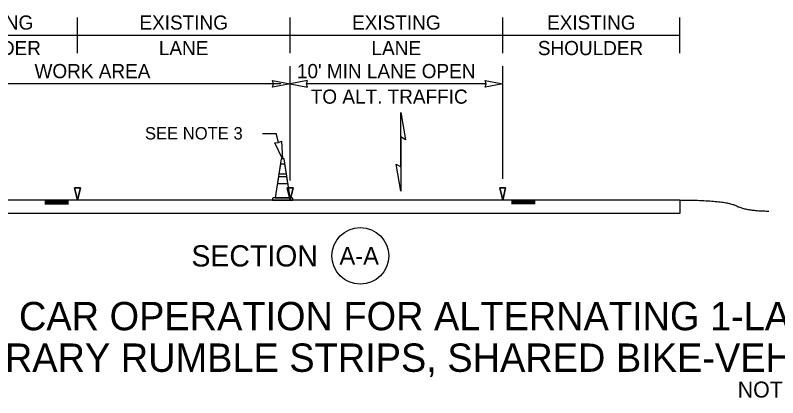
# Model space of a CAD drawing. Extents: x 99999.1 to 100095.7, y 99995 to 100010.7.
# Drawn here: x 100004.94 to 100009.243, y 100001.18 to 100003.339 of the extents above; entities that cross this region are included whole.
import ezdxf

# ---------------------------------------------------------------- set-up
doc = ezdxf.new("R2010")
doc.units = 0
for name, color, linetype in [('SH_DE_DetailHeading1Text', 7, 'Continuous'), ('TR_WZ_TrafficConeElev', 7, 'Continuous'), ('TR_WZ_WorkZoneDetails', 7, 'Continuous'), ('TR_WZ_WorkZoneTextCurrent', 7, 'Continuous')]:
    doc.layers.add(name, color=color, linetype=linetype)

msp = doc.modelspace()

# ---------------------------------------------------------------- linework, layer by layer
at = {"layer": 'TR_WZ_TrafficConeElev'}
for p, q in [((100006.4363, 100002.4976), (100006.428, 100002.4434)), ((100006.4616, 100002.4976), (100006.4363, 100002.4976)), ((100006.4699, 100002.4434), (100006.4616, 100002.4976)), ((100006.4255, 100002.4268), (100006.4197, 100002.3893)), ((100006.4724, 100002.4268), (100006.4255, 100002.4268)), ((100006.428, 100002.4434), (100006.4699, 100002.4434)), ((100006.4782, 100002.3893), (100006.4724, 100002.4268)), ((100006.4197, 100002.3893), (100006.4782, 100002.3893)), ((100006.3953, 100002.308), (100006.3911, 100002.3038)), ((100006.3911, 100002.3038), (100006.3911, 100002.2955)), ((100006.3911, 100002.2955), (100006.5068, 100002.2955)), ((100006.4073, 100002.308), (100006.3953, 100002.308)), ((100006.5068, 100002.3038), (100006.5026, 100002.308)), ((100006.5068, 100002.2955), (100006.5068, 100002.3038))]:
    msp.add_line(p, q, dxfattribs=at)
msp.add_lwpolyline([(100006.4073, 100002.308), (100006.4906, 100002.308), (100006.4568, 100002.5288), (100006.4411, 100002.5288)], close=True, dxfattribs=at)
msp.add_lwpolyline([(100006.4073, 100002.308), (100006.4906, 100002.308), (100006.4568, 100002.5288), (100006.4411, 100002.5288)], close=True, dxfattribs=at)
msp.add_lwpolyline([(100006.5026, 100002.308), (100006.4906, 100002.308), (100006.4073, 100002.308)], dxfattribs=at)
at = {"layer": 'TR_WZ_WorkZoneDetails'}
for p, q in [((100005.2907, 100003.1255), (100005.2907, 100003.3255)), ((100006.4907, 100003.1255), (100006.4907, 100003.3255)), ((100007.6907, 100003.1255), (100007.6907, 100003.3255)), ((100008.6907, 100003.1255), (100008.6907, 100003.3255)), ((100004.2907, 100003.2255), (100005.2907, 100003.2255)), ((100005.2907, 100003.2255), (100006.4907, 100003.2255)), ((100006.4907, 100003.2255), (100007.6907, 100003.2255)), ((100007.6907, 100003.2255), (100008.6907, 100003.2255)), ((100006.4907, 100002.4052), (100006.4907, 100003.0515)), ((100007.6907, 100002.4152), (100007.6907, 100003.0515)), ((100006.4387, 100002.9515), (100004.3844, 100002.9515)), ((100007.597, 100002.9515), (100006.5844, 100002.9515)), ((100006.3358, 100002.6715), (100006.412, 100002.6715)), ((100006.4255, 100002.6196), (100006.412, 100002.6715)), ((100007.1157, 100002.6519), (100007.1157, 100002.4831)), ((100007.1157, 100002.4831), (100007.1157, 100002.6519)), ((100008.6907, 100002.2954), (100004.2907, 100002.2954)), ((100005.1077, 100002.2902), (100005.2407, 100002.2902)), ((100005.1077, 100002.2846), (100005.2407, 100002.2846)), ((100005.1077, 100002.2789), (100005.2407, 100002.2789)), ((100007.8737, 100002.2898), (100007.7407, 100002.2898)), ((100007.8737, 100002.2842), (100007.7407, 100002.2842)), ((100007.8737, 100002.2785), (100007.7407, 100002.2785)), ((100008.6907, 100002.2954), (100008.6907, 100002.2204)), ((100005.1077, 100002.2737), (100005.2407, 100002.2737)), ((100007.8737, 100002.2733), (100007.7407, 100002.2733)), ((100008.6907, 100002.2204), (100004.2907, 100002.2204))]:
    msp.add_line(p, q, dxfattribs=at)
for points in [[(100006.4907, 100002.9515), (100006.3924, 100002.9322), (100006.397, 100002.9515), (100006.3924, 100002.9708)], [(100006.4907, 100002.9515), (100006.589, 100002.9322), (100006.5844, 100002.9515), (100006.589, 100002.9708)], [(100007.6907, 100002.9515), (100007.5924, 100002.9322), (100007.597, 100002.9515), (100007.5924, 100002.9708)], [(100007.1157, 100002.7895), (100007.1427, 100002.6363), (100007.1157, 100002.6519)], [(100006.449, 100002.5288), (100006.4057, 100002.6192), (100006.4255, 100002.6196), (100006.443, 100002.6288)], [(100007.1157, 100002.3454), (100007.0887, 100002.4987), (100007.1157, 100002.4831)], [(100005.2907, 100002.2954), (100005.274, 100002.3652), (100005.3073, 100002.3652)], [(100006.4907, 100002.2954), (100006.474, 100002.3652), (100006.5074, 100002.3652)], [(100007.6907, 100002.2954), (100007.674, 100002.3652), (100007.7073, 100002.3652)]]:
    msp.add_lwpolyline(points, close=True, dxfattribs=at)
for points in [[(100005.3073, 100002.3652), (100005.274, 100002.3652), (100005.2907, 100002.2954), (100005.3073, 100002.3652)], [(100006.5074, 100002.3652), (100006.474, 100002.3652), (100006.4907, 100002.2954), (100006.5074, 100002.3652)], [(100007.7073, 100002.3652), (100007.674, 100002.3652), (100007.6907, 100002.2954), (100007.7073, 100002.3652)]]:
    msp.add_lwpolyline(points, dxfattribs=at)
msp.add_circle((100006.8872, 100001.9805), 0.16, dxfattribs=at)
msp.add_open_spline([(100008.6907, 100002.2954), (100008.9419, 100002.2956), (100009.0674, 100002.2335), (100009.1928, 100002.2336)], degree=2, dxfattribs=at)

# ---------------------------------------------------------------- texts
at = {"layer": 'SH_DE_DetailHeading1Text'}
for s, height, p in [('PILOT CAR OPERATION FOR ALTERNATING 1-LANE, 2-WAY TRAFFIC: AFAD-CONTROLLED +', 0.16, (100004.2834, 100001.5606)), ('TEMPORARY RUMBLE STRIPS, SHARED BIKE-VEHICLE LANE STRATEGY (45+ MPH HIGHWAYS)', 0.16, (100004.1209, 100001.3259)), ('NOT TO SCALE', 0.09, (100009.0168, 100001.1809))]:
    msp.add_text(s, height=height, rotation=360, dxfattribs=at).set_placement(p)
at = {"layer": 'TR_WZ_WorkZoneDetails'}
for s, height, p in [('EXISTING', 0.08, (100004.5424, 100003.2575)), ('EXISTING', 0.08, (100005.6409, 100003.2575)), ('EXISTING', 0.08, (100006.8409, 100003.2575)), ('EXISTING', 0.08, (100007.9409, 100003.2575)), ('SHOULDER', 0.08, (100004.4905, 100003.1135)), ('LANE', 0.08, (100005.7503, 100003.1135)), ('LANE', 0.08, (100006.9503, 100003.1135)), ('SHOULDER', 0.08, (100007.889, 100003.1135)), ('SECTION', 0.12, (100005.9342, 100001.9205)), ('A-A', 0.1, (100006.7694, 100001.9305))]:
    msp.add_text(s, height=height, rotation=360, dxfattribs=at).set_placement(p)
for s, p in [('WORK AREA', (100005.0487, 100002.9835)), ("10' MIN LANE OPEN", (100006.5294, 100002.9835)), ('TO ALT. TRAFFIC', (100006.6075, 100002.8395))]:
    msp.add_text(s, height=0.08, dxfattribs=at).set_placement(p)
at = {"layer": 'TR_WZ_WorkZoneTextCurrent'}
msp.add_text('SEE NOTE 3', height=0.07, dxfattribs=at).set_placement((100005.672, 100002.6375))

doc.saveas('drawing.dxf')
